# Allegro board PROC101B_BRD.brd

Outline 177.8 x 141 mm; copper layers: TOP, L02_GND1, L03_SIG1, L04_GND2, L05_PWR1, L06_PWR2, L07_GND3, L08_SIG2, L09_GND4, BOTTOM. Coordinates in mm from the lower left corner of the outline.
Outline path: 0,134 0,141 177.8,141 177.8,134 ; 0,134 0,57.03 1.68,57.03 arc(1.82,56.97) 1.88,56.83 1.88,56.38 arc(1.82,56.24) 1.68,56.18 0,56.18 0,52.28 1.68,52.28 arc(1.82,52.22) 1.88,52.08 1.88,51.63 arc(1.82,51.49) 1.68,51.43 0,51.43 0,7 ; 0,134 177.8,134 ; 0,134 177.8,134 ; 177.8,134 177.8,44.11 177.3,43.61 176.2,43.61 arc(175.75,43.16) 176.2,42.71 177.3,42.71 177.8,42.21 177.8,39.36 177.3,38.86 176.2,38.86 arc(175.75,38.41) 176.2,37.96 177.3,37.96 177.8,37.46 177.8,26.96 177.3,26.46 176.2,26.46 arc(175.75,26.01) 176.2,25.56 177.3,25.56 177.8,25.06 177.8,22.21 177.3,21.71 176.2,21.71 arc(175.75,21.26) 176.2,20.81 177.3,20.81 177.8,20.31 177.8,7 ; 0,7 0,0 177.8,0 177.8,7 ; 0,7 177.8,7 ; 0,7 177.8,7

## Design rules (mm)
net group C1: nets C1N C1P
net group C2: nets C2N C2P
net group CLKGEN_REFCLK1N: nets CDC_Y1N CLKGEN_REFCLK1N
net group CLKGEN_REFCLK1P: nets CDC_Y1P CLKGEN_REFCLK1P
net group CPSW_RGMII1_ETH1_CLK: nets CPSW_RGMII1_ETH1_CLK N16248965
net group DDR_CLK: nets DDR_LDQS_N DDR_LDQS_P
net group DP1: nets SERDES_REFCLK0_N_C SERDES_REFCLK0_P_C
net group FT4232_USB_D: nets FT4232_USB_DM FT4232_USB_DP
net group GPMC0_WPN: nets GPMC0_WPN HSE_GPIO0_39
net group MCAN0: nets MCAN0_H MCAN0_L
net group MCAN1: nets MCAN1_H MCAN1_L
net group MCU_SPI0_CLK: nets MCU_SPI0_CLK MCU_SPI0_CLK_R
net group MMC0_CLK: nets MMC0_CLK SOC_MMC0_CLK
net group OSPI_DQS: nets OSPI_DQS OSPI_DQS_SOC
net group PRG0_HSE_ETH1_CLK: nets N16248899 PRG0_HSE_ETH1_CLK
net group PRG0_HSE_ETH2_CLK: nets N16248877 PRG0_HSE_ETH2_CLK
net group PRG1_RGMII1_ETH3_CLK: nets N16248921 PRG1_RGMII1_ETH3_CLK
net group PRG1_RGMII2_ETH2_CLK: nets N16248943 PRG1_RGMII2_ETH2_CLK
net group SERDES_RX: nets SERDES_RXN0 SERDES_RXP0
net group SERDES_TXN0: nets SERDES_TXN0 SERDES_TXN0_C
net group SERDES_TXP0: nets SERDES_TXP0 SERDES_TXP0_C
net group SOC_CLKIN: nets N16248855 SOC_CLKIN
net group SOC_TDO: nets N25395961 SOC_TDO
net group USB0_AB_D: nets USB0_AB_DM USB0_AB_DP
net group USB0_D: nets USB0_DM USB0_DP
net group XDS_USB_D: nets XDS_USB_DM XDS_USB_DP
net group BOOTMODE_U23-T: nets GPMC0_CLK
net group CLKGEN_REFCLK4N: nets CDC_Y4N CLKGEN_REFCLK4N PCIE_SERDES_REFCLK0_N
net group CLKGEN_REFCLK4P: nets CDC_Y4P CLKGEN_REFCLK4P PCIE_SERDES_REFCLK0_P
net group DDR_ADDR: nets DDR_ALERTN
net group DDR_ADDR-1: nets DDR_CSN DDR_ODT DDR_PARITY DDR_TEN
net group DDR_D8-15: nets DDR_DQ8 DDR_DQ9 DDR_DQ10 DDR_DQ11 DDR_DQ12 DDR_DQ13 DDR_DQ14 DDR_DQ15 DDR_UDM DDR_UDQS_N DDR_UDQS_P
net group DDR_DQ0-7: nets DDR_DQ0 DDR_DQ1 DDR_DQ2 DDR_DQ3 DDR_DQ4 DDR_DQ5 DDR_DQ6 DDR_DQ7 DDR_LDM
net group GPMC0_CSN0: nets HSE_GPIO0_41
net group MG1: nets CPSW_ETH1_D0M CPSW_ETH1_D0P CPSW_ETH1_D1M CPSW_ETH1_D1P CPSW_ETH1_D2M CPSW_ETH1_D2P CPSW_ETH1_D3M CPSW_ETH1_D3P
net group MG2: nets PRG0_PRU1GPO0 PRG0_PRU1GPO1 PRG0_PRU1GPO2 PRG0_PRU1GPO3 PRG0_PRU1GPO4 PRG0_PRU1GPO6
net group MG3: nets PRG0_PRU0GPO0 PRG0_PRU0GPO1 PRG0_PRU0GPO2 PRG0_PRU0GPO3 PRG0_PRU0GPO4 PRG0_PRU0GPO6
net group MG4: nets PRG0_PRU1GPO11 PRG0_PRU1GPO12 PRG0_PRU1GPO13 PRG0_PRU1GPO14 PRG0_PRU1GPO15 PRG0_PRU1GPO16
net group MG5: nets GPMC0_AD0 GPMC0_AD1 GPMC0_AD2 GPMC0_AD3 GPMC0_AD4 GPMC0_AD5 GPMC0_AD6 GPMC0_AD7 GPMC0_AD8/FSI_RX0_CLK GPMC0_AD9/FSI_RX0_D0 GPMC0_AD10/FSI_RX0_D1 GPMC0_AD11 GPMC0_AD12 GPMC0_AD13 GPMC0_AD14/FSI_TX0_D0 GPMC0_AD15/FSI_TX0_D1 HSE_GPIO0_31
net group MIPI_TRC: nets MIPI_TRC_DAT00 MIPI_TRC_DAT01 MIPI_TRC_DAT02 MIPI_TRC_DAT03 MIPI_TRC_DAT04 MIPI_TRC_DAT05 MIPI_TRC_DAT06 MIPI_TRC_DAT07 MIPI_TRC_DAT08 MIPI_TRC_DAT09 MIPI_TRC_DAT10 MIPI_TRC_DAT11 MIPI_TRC_DAT12 MIPI_TRC_DAT13 MIPI_TRC_DAT14 MIPI_TRC_DAT15 MIPI_TRC_DAT16 MIPI_TRC_DAT17 MIPI_TRC_DAT18 MIPI_TRC_DAT19 MIPI_TRC_DAT20 MIPI_TRC_DAT21
net group PRG0_RGMII1_TD: nets PRG0_PRU0GPO11 PRG0_PRU0GPO12 PRG0_PRU0GPO13 PRG0_PRU0GPO14 PRG0_PRU0GPO15 PRG0_PRU0GPO16
net group PRG1_ETH2: nets PRG1_ETH2_D0M PRG1_ETH2_D0P PRG1_ETH2_D1M PRG1_ETH2_D1P PRG1_ETH2_D2M PRG1_ETH2_D2P PRG1_ETH2_D3M PRG1_ETH2_D3P
net group PRG1_ETH3: nets PRG1_ETH3_D0M PRG1_ETH3_D0P PRG1_ETH3_D1M PRG1_ETH3_D1P PRG1_ETH3_D2M PRG1_ETH3_D2P PRG1_ETH3_D3M PRG1_ETH3_D3P
net group SOC_TCK: nets N16937764 N16938293 SOC_TCK

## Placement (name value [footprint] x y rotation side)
C1  4700pF  [CAP0402_0-75]  9.53 127.78 180 top
C2  4700pF  [CAP0402_0-75]  19.43 127.78 180 top
C3  0.1uF  [CAP0402_0-75]  16.26 126.13 90 top
C4  0.1uF  [CAP0402_0-75]  102.11 125.87 0 top
C5  0.1uF  [CAP0402_0-75]  141.86 125.87 90 top
C6  1uF  [CAP0402_0-75]  143.13 125.87 270 top
C7  0.1uF  [CAP0402_0-75]  124.46 125.74 0 top
C8  0.1uF  [CAP0402_0-75]  26.03 125.29 270 top
C9  10uF  [CAP0402_0-75]  97.41 116.06 0 top
C10  0.1uF  [CAP0402_0-75]  152.02 125.11 90 top
C11  1uF  [CAP0402_0-75]  75.18 124.47 270 top
C12  0.1uF  [CAP0402_0-75]  76.45 124.47 270 top
C13  0.1uF  [CAP0402_0-75]  77.72 124.47 270 top
C14  0.1uF  [CAP0402_0-75]  37.68 124.71 180 top
C15  1uF  [CAP0402_0-75]  81.59 123.32 180 top
C16  1uF  [CAP0402_0-75]  38.49 123.44 180 top
C17  0.1uF  [CAP0402_0-75]  84.84 122.44 270 top
C18  1uF  [CAP0402_0-75]  72.66 122.24 270 top
C19  0.1uF  [CAP0402_0-75]  73.9 122.24 270 top
C20  22uF  [CAP0603_1]  99.69 119.62 270 top
C21  0.1uF  [CAP0402_0-75]  101.22 119.62 90 top
C22  0.1uF  [CAP0402_0-75]  125.09 119.14 0 top
C23  0.1uF  [CAP0402_0-75]  12.7 118.63 0 top
C24  0.1uF  [CAP0402_0-75]  22.6 118.63 0 top
C25  10uF  [CAP0402_0-75]  29.46 116.73 270 top
C26  0.1uF  [CAP0402_0-75]  54.36 116.73 270 top
C27  0.01uF  [CAP0402_0-75]  105.23 116.39 180 top
C28  22uF  [CAP0603_1]  33.02 114.44 180 top
C29  0.1uF  [CAP0402_0-75]  8.51 112.79 90 top
C30  0.1uF  [CAP0402_0-75]  125.98 112.41 0 top
C31  0.1uF  [CAP0402_0-75]  155.57 111.27 180 top
C32  0.1uF  [CAP0402_0-75]  139.95 110.89 90 top
C33  22uF  [CAP0603_1]  155.69 109.26 0 top
C34  0.1uF  [CAP0402_0-75]  63.47 109.49 270 bottom
C35  0.1uF  [CAP0402_0-75]  40.17 106.95 90 top
C36  0.1uF  [CAP0402_0-75]  38.84 106.95 90 top
C37  10uF  [CAP0402_0-75]  159.13 104.79 90 top
C38  0.1uF  [CAP0402_0-75]  33.74 102.98 180 top
C39  0.1uF  [CAP0402_0-75]  33.74 101.48 180 top
C40  22uF  [CAP0603_1]  149.1 100.6 180 top
C41  0.1uF  [CAP0402_0-75]  45.56 100.59 0 top
C42  0.1uF  [CAP0201_0-5]  85.09 100.57 90 top
C43  0.1uF  [CAP0402_0-75]  33.74 99.98 180 top
C44  0.1uF  [CAP0402_0-75]  45.51 99.13 0 top
C45  0.1uF  [CAP0402_0-75]  123.95 98.95 180 top
C46  22uF  [CAP0603_1]  149.1 98.82 180 top
C47  0.1uF  [CAP0402_0-75]  127.38 97.93 180 top
C48  0.015uF  [CAP0402_0-75]  143.51 96.92 270 top
C49  150pF  [CAP0402_0-75]  144.78 96.92 90 top
C50  0.1uF  [CAP0402_0-75]  134.75 96.79 180 top
C51  0.1uF  [CAP0402_0-75]  41.91 95.77 270 top
C52  1uF  [CAP0402_0-75]  40.14 95.75 270 top
C53  0.01uF  [CAP0402_0-75]  75.82 95.11 90 top
C54  0.1uF  [CAP0402_0-75]  144.02 93.87 0 top
C55  0.1uF  [CAP0402_0-75]  141.6 93.23 270 top
C56  100uF_50V  [CAPAE_D8CASE_8]  165.47 87.1 270 top
C57  0.01uF  [CAP0402_0-75]  144.02 92.6 180 top
C58  1uF  [CAP0402_0-75]  84.26 93.49 270 top
C59  1uF  [CAP0402_0-75]  87.43 93.49 270 top
C60  1uF  [CAP0402_0-75]  88.7 93.49 270 top
C61  1uF  [CAP0402_0-75]  89.97 93.49 270 top
C62  1uF  [CAP0402_0-75]  91.24 93.49 270 top
C63  1uF  [CAP0402_0-75]  94.16 93.49 270 top
C64  1uF  [CAP0402_0-75]  98.81 97.54 0 top
C65  0.1uF  [CAP0402_0-75]  148.59 91.58 0 top
C66  10uF  [CAP0603_1]  148.46 90.06 180 top
C67  0.1uF  [CAP0402_0-75]  31.46 89.6 270 top
C68  1uF  [CAP0402_0-75]  41.78 87.52 90 top
C69  10uF  [CAP1206_2#2]  171.44 84.26 180 top
C70  470uF_10V  [CAPAE_875115252003_330X330_SMD_8-7]  145.7 83.88 0 top
C71  47uF  [CAP1206_2]  171.4 86.52 180 top
C72  0.1uF  [CAP0402_0-75]  132.21 85.22 180 top
C73  0.1uF  [CAP0402_0-75]  33.61 83.62 180 top
C74  4.7uF  [CAP0402_0-75]  108.25 85.42 270 top
C75  0.1uF  [CAP0201_0-5]  106.98 85.42 270 top
C76  0.1uF  [CAP0402_0-75]  33.61 82.12 180 top
C77  10uF  [CAP0402_0-75]  130.96 82.18 0 top
C78  0.1uF  [CAP0402_0-75]  45.43 81.23 0 top
C79  4.7uF  [CAP0402_0-75]  108.46 81.21 180 top
C80  0.1uF  [CAP0402_0-75]  33.61 80.62 180 top
C81  10uF  [CAP1206_2]  158.53 77.79 180 top
C82  10uF  [CAP1206_2]  163.27 77.79 0 top
C83  1uF  [CAP0402_0-75]  45.38 79.77 0 top
C84  22uF  [CAP1206_2#2]  147.09 78.29 0 top
C85  33pF  [CAP0402_0-75]  171.74 78.72 90 top
C86  1uF  [CAP0402_0-75]  107.7 78.37 90 top
C87  4.7uF  [CAP0402_0-75]  109.22 78.37 270 top
C88  4.7uF  [CAP0402_0-75]  72.14 74.34 270 bottom
C89  0.1uF  [CAP0402_0-75]  52.2 89.75 180 top
C90  0.1uF  [CAP0402_0-75]  38.87 76.38 270 top
C91  0.1uF  [CAP0201_0-5]  73.66 77.61 90 top
C92  0.1uF  [CAP0201_0-5]  74.42 77.61 90 top
C93  0.1uF  [CAP0201_0-5]  75.18 77.61 90 top
C94  33pF  [CAP0402_0-75]  148.72 75.45 270 top
C95  4.7uF  [CAP0603_1]  131.98 76.1 90 top
C96  120pF  [CAP0402_0-75]  138.58 76.1 270 top
C97  4.7uF  [CAP0402_0-75]  108.84 75.2 90 top
C98  1uF  [CAP0402_0-75]  107.31 75.07 270 top
C99  10uF  [CAP0402_0-75]  39.45 73.67 180 top
C100  0.22uF  [CAP0201_0-5]  74.85 71.36 0 top
C101  1uF  [CAP0402_0-75]  38.74 71.7 90 top
C102  0.22uF  [CAP0201_0-5]  74.85 70.47 0 top
C103  4.7uF  [CAP0402_0-75]  108.08 69.61 270 top
C104  0.1uF  [CAP0402_0-75]  45.25 68.35 0 top
C105  10uF  [CAP0402_0-75]  47.59 67.62 90 top
C106  1uF  [CAP0402_0-75]  33.52 67.5 180 top
C107  2.2uF  [CAP0603_1]  160.07 67.15 180 top
C108  2.2uF  [CAP0603_1]  163.07 67.15 0 top
C109  0.1uF  [CAP0402_0-75]  136.14 66.94 270 top
C110  1uF  [CAP0402_0-75]  45.28 66.89 0 top
C111  10uF  [CAP0402_0-75]  31.24 67.03 270 top
C112  1uF  [CAP0402_0-75]  33.52 66 180 top
C113  0.01uF  [CAP0402_0-75]  119.63 65.29 270 top
C114  1uF  [CAP0402_0-75]  33.52 64.5 180 top
C115  0.1uF  [CAP0402_0-75]  157.51 64.44 270 top
C116  0.1uF  [CAP0402_0-75]  166.22 64.16 90 top
C117  0.1uF  [CAP0402_0-75]  131.19 64.02 180 top
C118  0.01uF  [CAP0402_0-75]  152.02 62.99 270 top
C119  4.7uF  [CAP0402_0-75]  106.22 72.48 0 bottom
C120  4.7uF  [CAP0402_0-75]  89.28 58.69 270 top
C121  0.1uF  [CAP0201_0-5]  88.51 61.23 180 top
C122  22uF  [CAP0603_1]  19.05 62.5 0 top
C123  47uF  [CAP1206_2]  151.32 59.25 180 top
C124  0.1uF  [CAP0402_0-75]  41.66 60.59 270 top
C125  3900pF  [CAP0402_0-75]  169.22 60.16 0 top
C126  1uF  [CAP0402_0-75]  137.67 60.09 90 top
C127  10uF  [CAP0402_0-75]  22.61 59.83 90 top
C128  0.1uF  [CAP0402_0-75]  25.91 59.45 90 top
C129  2.2uF  [CAP0402_0-75]  133.22 59.45 90 top
C130  4.7pF  [CAP0402_0-75]  168.79 58.65 270 top
C131  0.056uF  [CAP0402_0-75]  156.96 57.07 270 top
C132  0.056uF  [CAP0402_0-75]  166.9 58.13 0 top
C133  12pF  [CAP0201_0-5]  99.72 58.77 180 top
C134  12pF  [CAP0201_0-5]  101.47 58.79 0 top
C135  33pF  [CAP0402_0-75]  155.17 55.53 90 top
C136  0.01uF  [CAP0402_0-75]  154.03 55.56 270 top
C137  1uF  [CAP0402_0-75]  160.07 56.23 90 top
C138  0.47uF  [CAP0603_1#2]  162.42 56.18 270 top
C139  0.1uF  [CAP0402_0-75]  32.97 49.54 0 top
C140  4.7uF  [CAP0402_0-75]  21.67 51.2 270 top
C141  10uF  [CAP0402_0-75]  31.19 52.34 270 top
C143  150uF_10V  [CAPT7343D_3-25]  15.44 43.88 0 top
C144  0.1uF  [CAP0402_0-75]  73.15 49.8 270 top
C145  0.1uF  [CAP0402_0-75]  90.81 49.67 180 top
C146  0.1uF  [CAP0402_0-75]  90.81 48.15 180 top
C147  0.1uF  [CAP0402_0-75]  44.36 48.06 270 bottom
C148  4.7uF  [CAP0402_0-75]  112.33 59.61 270 top
C149  1uF  [CAP0402_0-75]  118.01 60.8 270 top
C150  0.1uF  [CAP0402_0-75]  116.74 60.8 270 top
C151  0.1uF  [CAP0402_0-75]  140.72 45.94 180 top
C152  10uF  [CAP0402_0-75]  170.5 44.08 0 top
C153  1000pF  [CAP1206_1-75]  4.11 61.86 270 top
C154  0.1uF  [CAP0402_0-75]  170.75 42.43 0 top
C155  0.1uF  [CAP0402_0-75]  90.48 37.23 180 top
C156  0.1uF  [CAP0402_0-75]  93.59 35.19 270 top
C157  0.1uF  [CAP0402_0-75]  100.97 35.19 90 top
C158  2.2uF  [CAP0402_0-75]  164.34 35.07 180 top
C159  0.01uF  [CAP0402_0-75]  166.5 35.07 180 top
C160  1000pF  [CAP1206_1-75]  169.42 35.07 90 top
C161  0.1uF  [CAP0402_0-75]  64.49 32.55 180 top
C162  0.1uF  [CAP0402_0-75]  90.48 32.27 180 top
C163  0.1uF  [CAP0402_0-75]  93.59 31.64 270 top
C164  0.1uF  [CAP0402_0-75]  100.97 31.64 90 top
C165  0.1uF  [CAP0402_0-75]  103.61 31.64 90 top
C166  0.01uF  [CAP0402_0-75]  149.13 31.62 90 top
C167  1uF  [CAP0402_0-75]  152.52 31.24 180 top
C168  8.2pF  [CAP0402_0-75]  73.16 30.98 180 top
C169  8.2pF  [CAP0402_0-75]  78.75 30.98 180 top
C170  0.1uF  [CAP0402_0-75]  115.95 28.72 0 top
C171  0.1uF  [CAP0402_0-75]  138.43 28.72 180 top
C172  12pF  [CAP0201_0-5]  163.78 26.15 270 top
C173  0.1uF  [CAP0402_0-75]  120.65 27.57 270 top
C174  1uF  [CAP0402_0-75]  142.41 26.3 180 top
C175  0.01uF  [CAP0402_0-75]  162.31 26.18 90 top
C176  0.01uF  [CAP0402_0-75]  142.41 25.03 180 top
C177  12pF  [CAP0201_0-5]  163.78 24.88 90 top
C178  0.1uF  [CAP0402_0-75]  118.29 52.26 90 top
C179  0.1uF  [CAP0402_0-75]  120.15 24.05 90 top
C180  0.01uF  [CAP0402_0-75]  143.13 23.51 270 top
C181  0.1uF  [CAP0402_0-75]  66.34 23.26 0 top
C182  0.01uF  [CAP0402_0-75]  73.62 22.23 90 top
C183  0.01uF  [CAP0402_0-75]  79.21 22.23 90 top
C184  22uF  [CAP0805_1-5]  42.23 21.99 0 top
C185  0.1uF  [CAP0402_0-75]  163.86 21.77 90 top
C186  1uF  [CAP0402_0-75]  165.15 21.77 270 top
C187  2.2uF  [CAP0402_0-75]  166.41 21.77 270 top
C188  0.1uF  [CAP0402_0-75]  138.56 21.6 0 top
C189  0.1uF  [CAP0402_0-75]  120.07 49.47 180 top
C190  0.01uF  [CAP0402_0-75]  96.44 21.12 270 top
C191  0.01uF  [CAP0402_0-75]  162.43 21.1 90 top
C192  0.1uF  [CAP0402_0-75]  143.65 16.46 90 top
C193  0.1uF  [CAP0402_0-75]  162.47 16.01 90 top
C194  0.1uF  [CAP0402_0-75]  107.81 14.57 270 top
C195  2.2uF  [CAP0402_0-75]  165.35 13.98 90 top
C196  0.1uF  [CAP0402_0-75]  152.67 12.32 180 top
C197  1uF  [CAP0402_0-75]  165.23 10.3 270 top
C198  15pF  [CAP0402_0-75]  163.45 9.54 180 top
C199  0.1uF  [CAP0402_0-75]  91.95 131.46 180 bottom
C200  0.01uF  [CAP0402_0-75]  89.15 126.25 180 bottom
C201  2.2uF  [CAP0402_0-75]  91.95 126.13 0 bottom
C202  0.01uF  [CAP0402_0-75]  97.41 116.06 0 bottom
C203  0.1uF  [CAP0402_0-75]  87 124.35 180 bottom
C204  0.1uF  [CAP0402_0-75]  150.67 122.82 180 bottom
C205  0.1uF  [CAP0402_0-75]  38.5 122.15 180 top
C206  0.1uF  [CAP0402_0-75]  72.63 122.24 270 bottom
C207  0.1uF  [CAP0402_0-75]  43.3 121.71 180 bottom
C208  10uF  [CAP0402_0-75]  75.82 120.66 90 bottom
C209  0.1uF  [CAP0402_0-75]  102.69 121.31 90 bottom
C210  10uF  [CAP0402_0-75]  78.87 119.9 180 bottom
C211  10uF  [CAP0603_1]  142.24 119.39 270 bottom
C212  1uF  [CAP0402_0-75]  71.12 119.06 180 bottom
C213  0.1uF  [CAP0402_0-75]  74.68 117.36 0 bottom
C214  0.1uF  [CAP0402_0-75]  131.57 116.85 180 bottom
C215  0.01uF  [CAP0402_0-75]  29.46 116.73 270 bottom
C216  1uF  [CAP0402_0-75]  38.84 116.08 180 bottom
C217  22uF  [CAP0603_1]  142.62 115.71 0 bottom
C218  0.22uF  [CAP0201_0-5]  77.85 113.17 180 bottom
C219  0.01uF  [CAP0402_0-75]  75.69 113.17 180 bottom
C220  0.1uF  [CAP0402_0-75]  46.31 113.13 180 bottom
C221  0.1uF  [CAP0402_0-75]  135 112.16 270 bottom
C222  0.01uF  [CAP0201_0-5]  94 110.83 180 bottom
C223  0.01uF  [CAP0201_0-5]  87.61 110.83 0 bottom
C224  0.01uF  [CAP0201_0-5]  88.41 110.03 180 bottom
C225  1uF  [CAP0402_0-75]  66.04 109.49 270 bottom
C226  0.1uF  [CAP0402_0-75]  64.77 109.49 270 bottom
C227  0.1uF  [CAP0201_0-5]  86.49 109.36 90 bottom
C228  2.2uF  [CAP0402_0-75]  85.47 109.36 270 bottom
C229  0.01uF  [CAP0201_0-5]  94.68 109.35 270 bottom
C230  22uF  [CAP0603_1]  96.27 109.11 270 bottom
C232  0.01uF  [CAP0201_0-5]  94.68 107.75 270 bottom
C233  0.01uF  [CAP0201_0-5]  86.93 107.75 270 bottom
C234  0.01uF  [CAP0201_0-5]  73.41 107.33 180 bottom
C235  0.1uF  [CAP0402_0-75]  65.66 107.33 90 bottom
C236  0.01uF  [CAP0201_0-5]  93.88 106.95 90 bottom
C237  1uF  [CAP0402_0-75]  40.17 106.92 90 bottom
C238  1uF  [CAP0402_0-75]  38.84 106.92 90 bottom
C239  0.01uF  [CAP0201_0-5]  87.61 106.83 180 bottom
C241  0.01uF  [CAP0201_0-5]  93.2 106.03 0 bottom
C242  0.01uF  [CAP0201_0-5]  86.93 105.35 270 bottom
C243  1uF  [CAP0402_0-75]  142.62 105.04 0 bottom
C244  1uF  [CAP0402_0-75]  81.28 104.92 180 bottom
C245  0.01uF  [CAP0402_0-75]  175.39 104.41 0 bottom
C246  1uF  [CAP0402_0-75]  81.28 103.65 180 bottom
C247  10pF  [CAP0402_0-75]  54.74 103.52 180 bottom
C248  0.01uF  [CAP0201_0-5]  98.93 103.01 0 bottom
C249  1uF  [CAP0402_0-75]  33.77 102.98 180 bottom
C250  0.01uF  [CAP0201_0-5]  86.93 102.95 270 bottom
C251  1uF  [CAP0402_0-75]  81.28 102.38 180 bottom
C252  0.1uF  [CAP0402_0-75]  64.9 101.61 180 bottom
C253  1uF  [CAP0402_0-75]  33.77 101.48 180 bottom
C254  1uF  [CAP0402_0-75]  81.28 101.11 180 bottom
C255  10pF  [CAP0402_0-75]  61.72 100.85 270 bottom
C256  10pF  [CAP0402_0-75]  60.45 100.85 270 bottom
C257  10pF  [CAP0402_0-75]  59.18 100.85 270 bottom
C258  10uF  [CAP0402_0-75]  31.5 100.45 90 bottom
C259  1uF  [CAP0402_0-75]  45.53 100.59 0 bottom
C260  0.1uF  [CAP0402_0-75]  56.26 100.03 0 bottom
C261  1uF  [CAP0402_0-75]  33.77 99.98 180 bottom
C262  10pF  [CAP0402_0-75]  62.99 99.96 270 bottom
C263  10uF  [CAP0402_0-75]  47.46 100.11 270 bottom
C264  1uF  [CAP0402_0-75]  81.28 99.84 180 bottom
C265  1uF  [CAP0402_0-75]  142.24 99.71 270 bottom
C266  1uF  [CAP0402_0-75]  45.5 99.13 0 bottom
C267  1uF  [CAP0402_0-75]  81.28 98.57 180 bottom
C268  0.01uF  [CAP0201_0-5]  86.93 98.15 270 bottom
C269  0.1uF  [CAP0402_0-75]  138.18 97.8 180 bottom
C270  0.1uF  [CAP0201_0-5]  94.39 96.92 0 bottom
C271  0.1uF  [CAP0402_0-75]  172.86 96.66 180 bottom
C272  200pF  [CAP0402_0-75]  154.69 95.9 270 bottom
C274  1uF  [CAP0402_0-75]  41.91 95.8 270 bottom
C275  0.1uF  [CAP0402_0-75]  40.14 95.72 270 bottom
C276  0.1uF  [CAP0402_0-75]  49.4 95.26 270 bottom
C277  2700pF  [CAP0603_1]  131.7 94.76 90 bottom
C278  0.1uF  [CAP0402_0-75]  108.89 93.35 180 bottom
C279  0.1uF  [CAP0402_0-75]  108.89 94.63 180 bottom
C280  1uF  [CAP0402_0-75]  44.26 94.38 90 bottom
C281  10uF  [CAP0402_0-75]  39.07 93.8 180 bottom
C283  0.1uF  [CAP0402_0-75]  131.57 92.6 180 bottom
C284  0.1uF  [CAP0402_0-75]  56.26 92.03 0 bottom
C285  0.1uF  [CAP0402_0-75]  108.92 95.9 180 bottom
C286  1uF  [CAP0402_0-75]  46.92 90.95 180 bottom
C287  1000pF  [CAP1206_1-75]  11.56 90.75 270 bottom
C288  10uF  [CAP0402_0-75]  100.2 90.44 0 bottom
C289  1uF  [CAP0201_0-5]  94.01 78.03 270 bottom
C290  4.7uF  [CAP0402_0-75]  100.2 88.66 0 bottom
C291  0.1uF  [CAP0402_0-75]  116.87 82.01 0 bottom
C292  0.1uF  [CAP0402_0-75]  116.87 80.71 0 bottom
C293  0.1uF  [CAP0402_0-75]  41.78 87.52 90 bottom
C294  1uF  [CAP0402_0-75]  100.2 87.14 0 bottom
C295  1000pF  [CAP1206_1-75]  2.24 88.24 90 bottom
C296  0.1uF  [CAP0402_0-75]  116.81 79.44 0 bottom
C297  1uF  [CAP0402_0-75]  33.64 83.62 180 bottom
C298  1uF  [CAP0201_0-5]  87.01 80.98 0 bottom
C299  4.7uF  [CAP0402_0-75]  104.83 78.62 270 bottom
C300  0.1uF  [CAP0201_0-5]  103.58 78.6 270 bottom
C301  1uF  [CAP0402_0-75]  33.64 82.12 180 bottom
C302  0.1uF  [CAP0201_0-5]  93.46 81.78 0 bottom
C303  0.1uF  [CAP0201_0-5]  91.86 81.78 0 bottom
C304  0.1uF  [CAP0201_0-5]  88.66 81.78 180 bottom
C305  10uF  [CAP0402_0-75]  31.37 81.09 90 bottom
C306  1uF  [CAP0402_0-75]  45.4 81.23 0 bottom
C307  0.1uF  [CAP0201_0-5]  94.93 81.1 270 bottom
C308  0.1uF  [CAP0201_0-5]  90.93 81.1 270 bottom
C309  0.1uF  [CAP0201_0-5]  90.13 81.1 90 bottom
C310  0.1uF  [CAP0201_0-5]  93.46 80.98 180 bottom
C311  0.1uF  [CAP0201_0-5]  91.86 80.98 180 bottom
C312  0.1uF  [CAP0201_0-5]  88.66 80.98 0 bottom
C313  1uF  [CAP0402_0-75]  33.64 80.62 180 bottom
C314  0.1uF  [CAP0201_0-5]  95.73 80.3 270 bottom
C315  0.1uF  [CAP0201_0-5]  88.62 80.18 180 bottom
C316  10uF  [CAP0402_0-75]  47.71 80.49 270 bottom
C317  0.1uF  [CAP0201_0-5]  93.46 80.18 0 bottom
C318  0.1uF  [CAP0201_0-5]  91.86 80.18 0 bottom
C319  0.1uF  [CAP0201_0-5]  87.06 80.18 180 bottom
C320  0.1uF  [CAP0402_0-75]  45.37 79.77 0 bottom
C321  0.1uF  [CAP0201_0-5]  94.93 79.5 270 bottom
C322  0.01uF  [CAP0201_0-5]  94.13 79.5 90 bottom
C323  0.1uF  [CAP0201_0-5]  90.13 79.5 90 bottom
C324  0.1uF  [CAP0201_0-5]  91.86 79.38 180 bottom
C325  0.1uF  [CAP0201_0-5]  88.66 79.38 0 bottom
C326  0.1uF  [CAP0201_0-5]  87.06 79.38 0 bottom
C327  4.7uF  [CAP0402_0-75]  76.71 81.19 270 bottom
C328  0.1uF  [CAP0201_0-5]  95.73 78.7 270 bottom
C329  0.1uF  [CAP0201_0-5]  93.33 78.7 90 bottom
C330  0.1uF  [CAP0201_0-5]  91.18 78.7 90 bottom
C331  0.1uF  [CAP0201_0-5]  94.93 78.58 0 bottom
C332  0.1uF  [CAP0201_0-5]  89.46 78.58 0 bottom
C333  0.1uF  [CAP0201_0-5]  87.86 78.58 0 bottom
C334  10uF  [CAP0402_0-75]  103.9 86.02 0 bottom
C335  4.7uF  [CAP0402_0-75]  103.9 84.75 0 bottom
C336  1uF  [CAP0402_0-75]  103.9 83.48 0 bottom
C337  0.1uF  [CAP0201_0-5]  95.86 77.78 0 bottom
C338  0.1uF  [CAP0201_0-5]  94.51 77.1 180 bottom
C339  0.1uF  [CAP0201_0-5]  89.46 77.78 180 bottom
C340  0.1uF  [CAP0201_0-5]  77.98 81.19 270 bottom
C341  4.7uF  [CAP0402_0-75]  76.28 77.61 0 bottom
C342  0.1uF  [CAP0201_0-5]  90.38 77.23 270 bottom
C343  0.1uF  [CAP0201_0-5]  95.86 77.23 0 bottom
C344  0.01uF  [CAP0201_0-5]  88.66 77.23 0 bottom
C345  0.1uF  [CAP0201_0-5]  91.98 77.22 270 bottom
C346  0.1uF  [CAP0201_0-5]  91.18 77.22 270 bottom
C347  0.01uF  [CAP0201_0-5]  93.46 77.1 0 bottom
C348  1uF  [CAP0201_0-5]  87.06 77.5 180 bottom
C349  1uF  [CAP0402_0-75]  38.87 76.41 270 bottom
C350  0.01uF  [CAP0201_0-5]  86.38 76.21 90 bottom
C351  0.1uF  [CAP0201_0-5]  94.93 76.18 90 bottom
C352  0.1uF  [CAP0201_0-5]  93.33 76.18 90 bottom
C353  0.01uF  [CAP0201_0-5]  92.53 76.18 90 bottom
C354  0.1uF  [CAP0201_0-5]  91.06 76.18 180 bottom
C355  0.01uF  [CAP0201_0-5]  89.46 76.18 0 bottom
C356  0.01uF  [CAP0201_0-5]  87.86 76.18 180 bottom
C357  1uF  [CAP0201_0-5]  88.78 74.58 90 bottom
C358  0.1uF  [CAP0201_0-5]  81.67 76.43 180 bottom
C359  0.1uF  [CAP0201_0-5]  96.53 75.5 270 bottom
C360  0.1uF  [CAP0201_0-5]  87.18 75.5 90 bottom
C361  0.1uF  [CAP0201_0-5]  95.73 75.38 0 bottom
C362  0.01uF  [CAP0201_0-5]  88.66 75.38 0 bottom
C363  4.7uF  [CAP0402_0-75]  111.51 75.2 90 bottom
C364  4.7uF  [CAP0402_0-75]  104.98 75.15 90 bottom
C365  0.1uF  [CAP0201_0-5]  115.95 75.07 0 bottom
C366  1uF  [CAP0402_0-75]  103.48 75.07 270 bottom
C367  0.1uF  [CAP0201_0-5]  110.11 75.06 90 bottom
C368  0.01uF  [CAP0201_0-5]  92.78 74.83 270 bottom
C369  10uF  [CAP0402_0-75]  38.6 74.82 180 bottom
C370  0.1uF  [CAP0201_0-5]  93.66 74.91 225 bottom
C371  0.1uF  [CAP0201_0-5]  89.66 74.5 135 bottom
C372  0.1uF  [CAP0201_0-5]  90.81 74.31 180 bottom
C373  0.01uF  [CAP0201_0-5]  93.46 74.03 180 bottom
C374  0.1uF  [CAP0201_0-5]  95.73 73.9 270 bottom
C375  0.01uF  [CAP0201_0-5]  87.26 74.11 225 bottom
C376  0.1uF  [CAP0201_0-5]  95.05 73.88 315 bottom
C377  4.7uF  [CAP0402_0-75]  115.95 73.8 0 bottom
C378  0.1uF  [CAP0201_0-5]  88.54 73.23 0 bottom
C379  0.1uF  [CAP0201_0-5]  89.46 73.78 180 bottom
C380  0.01uF  [CAP0201_0-5]  87.26 73.31 225 bottom
C381  0.1uF  [CAP0201_0-5]  91.71 72.98 270 bottom
C382  0.1uF  [CAP0201_0-5]  94.26 73.1 315 bottom
C383  0.1uF  [CAP0201_0-5]  92.55 72.98 0 bottom
C384  0.1uF  [CAP0402_0-75]  72.15 71.25 0 bottom
C385  0.1uF  [CAP0402_0-75]  38.74 71.73 90 bottom
C387  0.1uF  [CAP0201_0-5]  106.79 69.53 270 top
C388  0.1uF  [CAP0402_0-75]  72.15 69.98 0 bottom
C389  1uF  [CAP0402_0-75]  45.25 68.35 0 bottom
C390  1uF  [CAP0201_0-5]  94.13 76.18 90 bottom
C391  1uF  [CAP0201_0-5]  91.26 75.3 135 bottom
C392  0.1uF  [CAP0402_0-75]  33.49 67.5 180 bottom
C393  0.1uF  [CAP0402_0-75]  139.32 67.45 180 bottom
C394  0.1uF  [CAP0402_0-75]  45.31 66.89 0 bottom
C395  0.1uF  [CAP0402_0-75]  33.49 66 180 bottom
C396  1uF  [CAP0201_0-5]  89.66 72.9 135 bottom
C397  0.1uF  [CAP0402_0-75]  33.49 64.5 180 bottom
C398  4.7uF  [CAP0402_0-75]  89.33 61.2 180 bottom
C399  0.1uF  [CAP0201_0-5]  87.76 62.49 270 bottom
C400  3.3uF  [CAP0603_1]  92.56 67.79 90 bottom
C401  1uF  [CAP0402_0-75]  41.66 60.59 270 bottom
C402  0.01uF  [CAP0402_0-75]  22.61 59.83 90 bottom
C403  0.01uF  [CAP0402_0-75]  140.59 57.16 0 bottom
C404  0.1uF  [CAP0402_0-75]  79.25 56.91 90 bottom
C405  0.1uF  [CAP0402_0-75]  79.25 54.5 270 bottom
C406  0.01uF  [CAP0402_0-75]  170.94 53.86 0 bottom
C407  0.1uF  [CAP0402_0-75]  139.19 53.35 0 bottom
C408  0.1uF  [CAP0402_0-75]  132.08 51.83 0 bottom
C409  0.1uF  [CAP0402_0-75]  140.34 51.32 90 bottom
C410  0.1uF  [CAP0402_0-75]  113.54 50.78 270 bottom
C411  0.1uF  [CAP0402_0-75]  60.96 50.69 90 bottom
C412  0.1uF  [CAP0402_0-75]  138.68 50.43 270 bottom
C413  0.1uF  [CAP0402_0-75]  144.4 50.05 180 bottom
C414  0.1uF  [CAP0402_0-75]  133.22 48.91 90 bottom
C415  4.7uF  [CAP0402_0-75]  99.8 47.36 180 bottom
C416  0.1uF  [CAP0402_0-75]  132.59 46.5 0 bottom
C417  0.1uF  [CAP0402_0-75]  110.87 46.26 270 bottom
C418  0.1uF  [CAP0402_0-75]  99.8 46.08 180 bottom
C419  0.1uF  [CAP0402_0-75]  148.08 44.97 270 bottom
C420  0.1uF  [CAP0402_0-75]  132.59 44.97 0 bottom
C421  0.1uF  [CAP0402_0-75]  27.05 44.34 270 bottom
C422  0.1uF  [CAP0402_0-75]  132.84 43.32 270 bottom
C423  0.1uF  [CAP0402_0-75]  148.72 41.92 180 bottom
C424  0.1uF  [CAP0402_0-75]  154.69 41.54 270 bottom
C425  0.1uF  [CAP0402_0-75]  132.84 41.42 270 bottom
C426  0.1uF  [CAP0402_0-75]  35.43 40.27 90 bottom
C427  0.1uF  [CAP0402_0-75]  116 39.84 90 bottom
C428  1uF  [CAP0402_0-75]  114.15 39.84 90 bottom
C429  0.1uF  [CAP0402_0-75]  155.07 39.77 180 bottom
C430  2.2uF  [CAP0402_0-75]  118.01 39.64 180 bottom
C431  0.1uF  [CAP0402_0-75]  11.05 39 90 bottom
C432  0.01uF  [CAP0402_0-75]  9.53 39 90 bottom
C433  18pF  [CAP0402_0-75]  132.33 38.95 270 bottom
C434  0.1uF  [CAP0402_0-75]  104.27 37.99 270 bottom
C435  0.1uF  [CAP0402_0-75]  20.07 37.99 90 bottom
C436  0.01uF  [CAP0402_0-75]  18.8 37.99 90 bottom
C437  0.1uF  [CAP0402_0-75]  118.4 37.1 0 bottom
C438  2.2uF  [CAP0402_0-75]  120.52 36.67 90 bottom
C439  18pF  [CAP0402_0-75]  132.33 36.16 90 bottom
C440  0.1uF  [CAP0402_0-75]  136.4 35.07 90 bottom
C441  3.3uF  [CAP0603_1]  144.5 34.25 270 bottom
C442  0.1uF  [CAP0402_0-75]  140.97 34.81 90 bottom
C443  0.1uF  [CAP0402_0-75]  118.24 32.48 0 bottom
C444  0.01uF  [CAP0402_0-75]  59.94 31.89 180 bottom
C445  0.1uF  [CAP0402_0-75]  127.38 31 270 bottom
C446  0.1uF  [CAP0402_0-75]  45.97 30.24 270 bottom
C447  0.1uF  [CAP0402_0-75]  160.99 30.24 270 bottom
C448  47uF  [CAP1206_2]  5.33 26.94 180 bottom
C449  0.1uF  [CAP0402_0-75]  10.92 26.43 270 bottom
C450  0.01uF  [CAP0402_0-75]  9.65 26.43 270 bottom
C451  2.2uF  [CAP0402_0-75]  40.77 26.18 180 bottom
C452  2.2uF  [CAP0603_1]  56.64 25.29 180 bottom
C453  0.1uF  [CAP0402_0-75]  143.13 23.51 90 bottom
C454  1uF  [CAP0402_0-75]  7.87 23.26 90 bottom
C455  0.1uF  [CAP0402_0-75]  24.03 22.48 0 bottom
C456  0.01uF  [CAP0402_0-75]  77.31 22.23 90 bottom
C457  0.01uF  [CAP0402_0-75]  71.72 22.23 90 bottom
C458  22uF  [CAP0805_1-5]  54.86 21.48 90 bottom
C459  1uF  [CAP0402_0-75]  15.62 21.48 90 bottom
C460  1uF  [CAP0402_0-75]  8.64 21.35 90 bottom
C461  0.1uF  [CAP0402_0-75]  123.14 57.47 270 bottom
C462  1uF  [CAP0402_0-75]  6.99 20.08 180 bottom
C463  1uF  [CAP0402_0-75]  6.99 18.76 180 bottom
C464  0.1uF  [CAP0402_0-75]  123.4 53.24 180 bottom
C465  0.1uF  [CAP0402_0-75]  123.57 18.05 90 bottom
C466  0.1uF  [CAP0402_0-75]  132.47 17.9 90 bottom
C467  0.1uF  [CAP0402_0-75]  116.02 17.86 90 bottom
C468  0.1uF  [CAP0402_0-75]  138.29 17.43 90 bottom
C469  0.1uF  [CAP0402_0-75]  82.04 17.29 180 bottom
C470  1uF  [CAP0402_0-75]  24.26 16.27 180 bottom
C471  1uF  [CAP0402_0-75]  15.24 16.14 180 bottom
C472  0.1uF  [CAP0402_0-75]  82.02 15.99 180 bottom
C473  4.7uF  [CAP0603_1]  8.76 15.76 0 bottom
C474  2.2uF  [CAP0603_1]  8.64 10.99 270 bottom
C475  0.1uF  [CAP0201_0-5]  90.47 75.3 90 bottom
C476  0.1uF  [CAP0402_0-75]  94.39 42.56 90 top
C477  0.1uF  [CAP0402_0-75]  102.13 38.42 0 top
C478  1000pF  [CAP1206_1-75]  172.82 108.42 270 bottom
C479  0.1uF  [CAP0402_0-75]  113.75 109.22 180 top
C482  47uF  [CAP1206_2]  120.11 100.07 90 top
C483  0.1uF  [CAP0201_0-5]  121.63 99.43 90 top
C484  0.1uF  [CAP0201_0-5]  122.52 99.43 90 top
C485  0.1uF  [CAP0402_0-75]  126.75 48.39 90 top
C486  10uF  [CAP0402_0-75]  131.7 83.69 0 top
C487  10pF  [CAP0402_0-75]  112.9 80.53 0 bottom
C488  10pF  [CAP0402_0-75]  108.95 85.3 90 bottom
C491  10pF  [CAP0402_0-75]  100.73 64.13 270 bottom
C492  10pF  [CAP0402_0-75]  102.6 67.46 270 bottom
C493  10pF  [CAP0402_0-75]  105.39 66.94 270 bottom
C494  0.1uF  [CAP0402_0-75]  133.44 99.45 90 top
C495  0.1uF  [CAP0402_0-75]  123.57 103.62 180 top
C509  0.47uF  [CAP0402_0-75]  53.49 50.63 270 top
C513  0.47uF  [CAP0402_0-75]  45.26 51.67 270 top
C517  0.47uF  [CAP0402_0-75]  51.97 60.92 0 top
C519  0.47uF  [CAP0402_0-75]  49.94 60.92 180 top
C520  4.7uF  [CAP0402_0-75]  46.41 51.67 270 top
C521  4.7uF  [CAP0402_0-75]  52.35 50.63 270 top
C522  4.7uF  [CAP0402_0-75]  51.97 59.77 0 top
C523  4.7uF  [CAP0402_0-75]  49.94 59.77 180 top
C524  0.1uF  [CAP0402_0-75]  51.21 50.63 270 top
C525  0.1uF  [CAP0402_0-75]  51.97 58.63 0 top
C526  0.1uF  [CAP0402_0-75]  49.94 58.63 180 top
C527  0.1uF  [CAP0402_0-75]  47.55 51.67 270 top
C529  0.1uF  [CAP0402_0-75]  78.65 39.73 180 top
C532  27pF  [CAP0402_0-75]  47.65 50.12 0 top
C533  27pF  [CAP0402_0-75]  49.56 50.12 180 top
C534  0.1uF  [CAP0402_0-75]  111.22 109.67 270 bottom
C535  2700pF  [CAP0603_1]  110.26 107.97 180 bottom
C536  1uF  [CAP0402_0-75]  58.93 108.86 180 top
C537  0.1uF  [CAP0402_0-75]  60.93 108.86 180 top
C538  0.1uF  [CAP0402_0-75]  58.93 103.76 180 top
C539  2.2uF  [CAP0603_1]  164.64 60.45 270 bottom
D1  SMCJ64CA  [DIO_SMC]  172.03 103.34 0 top
D2  S1G-13-F  [DIO_SMA]  159.95 99.2 90 top
D3  PMEG045V150EPDAZ  [CFP15_PMEG045V150EPD_0-9]  169.85 95.6 270 top
D4  XBS104S13R  [DIO_SOD323_1]  159.09 70.58 0 top
D5  XBS104S13R  [DIO_SOD323_1]  164.05 70.58 180 top
D6  TPD1E10B06DPYR  [DIO_DFN0402_0-5]  170.63 45.73 0 top
D7  BZX84C6V8LT1G  [SOT23-123_1-2]  3.94 38.88 90 bottom
D8  TPD1E10B06DPYR  [DIO_DFN0402_0-5]  121.92 17.92 90 bottom
D9  TPD1E10B06DPYR  [DIO_DFN0402_0-5]  129.29 17.78 90 bottom
D10  TPD1E10B06DPYR  [DIO_DFN0402_0-5]  136.73 17.69 90 bottom
D11  TPD1E10B06DPYR  [DIO_DFN0402_0-5]  114.63 17.61 90 bottom
F1  10A  [FUSE_397_410X110_SMD_2-9]  164.39 103.67 270 top
FB1  120E  [IND0603_1]  17.17 123.2 180 top
FB2  120E  [IND0603_1]  24.09 116.98 180 top
FB3  120E  [IND0603_1]  110.03 85.42 90 top
FB4  26E  [IND0603_1]  72.49 78.53 0 bottom
FB5  120E  [IND0603_1]  109.86 69.61 90 top
FB6  120E  [IND0603_1]  91.06 58.56 90 top
FB8  120E  [IND0603_1]  170.75 26.68 180 top
FB9  120E  [IND0603_1]  41.4 25.29 90 top
FB11  120E  [IND0603_1]  83.19 109.87 0 bottom
FB12  120E  [IND0603_1]  67.97 109.49 180 bottom
FB13  120E  [IND0603_1]  108.66 80.25 270 bottom
FB14  120E  [IND0603_1]  26.11 77.55 180 bottom
FB15  120E  [IND0603_1]  72.39 82.84 0 bottom
FB16  26E  [IND0603_1]  72.47 81.07 0 bottom
FB17  26E  [IND0603_1]  115.95 71.49 180 bottom
FB18  120E  [IND0603_1]  111.25 71.34 90 bottom
FB19  120E  [IND0603_1]  26.78 72.18 180 bottom
FB20  120E  [IND0603_1]  91.29 59.55 180 bottom
FB21  120E  [IND0603_1]  59.18 51.81 90 bottom
FB23  220E  [IND0402_0-6]  130.94 42.94 180 bottom
FB24  220E  [IND0402_0-6]  130.94 41.16 180 bottom
FB25  120E  [IND0603_1]  61.61 111.35 180 top
FB26  120E  [IND0603_1]  12.71 111.96 0 top
FL7  4.7uF  [EMIFIL_NFM21P_0805_1]  33.48 52.08 90 top
FL17  0.47uF  [EMIFIL_NFM21P_0805]  49.41 62.82 0 top
FL18  0.47uF  [EMIFIL_NFM21P_0805]  53.35 62.82 180 top
FL19  0.47uF  [EMIFIL_NFM21P_0805]  55.52 50.12 90 top
FL20  0.47uF  [EMIFIL_NFM21P_0805]  43.33 51.39 90 top
FL22  90E  [IND4_ACM2012_90X50_SMD_1-3]  8.48 56.53 180 bottom
J1  HDR_2X12  [HDR_2X12_TSW-112-07-D_S_T_8-6]  141.73 128.67 0 top
J2  CON_XMC_5X30_F  [CON_XMC5X30_SEAF-30-06-05-2-A_S_S_S_6-4]  55.5 129.81 180 top
J3  HDR_2X10  [HDR_2X10_TSW_100_S_T]  104.65 128.16 180 top
J4  HDR_1X5  [HDR_5X1_100_S_T_11-2]  129.16 124.73 180 top
J5  HDR_1X3  [HDR_3X1_100_S_T]  109.93 124.39 0 top
J6  CON_PWRJACK2_PJ-080BH  [CON_PWRJACK2_PJ-080BH_P_R_T_13-4]  164.62 117.64 90 top
J7  HDR_2X5  [HDR_5X2_100_S_T_8-6]  3.56 123.33 90 top
J8  HDR_2X1  [HDR_2X1_100_S_T_10-8]  88.65 116.6 0 top
J9  HDR_1X2  [HDR_1X2_68002-202_S_T_8-6]  24.51 114.57 0 top
J10  HDR_1X2  [HDR_1X2_68002-202_S_T_8-6]  13.84 114.19 0 top
J11  HDR_2X1  [HDR_2X1_100_S_T_10-8]  151.89 113.3 0 top
J12  HDR_2X1  [HDR_2X1_100_S_T]  122.3 113.81 90 top
J13  HDR_2X1  [HDR_2X1_100_S_T_10-8]  132.84 108.85 0 top
J14  CON_RJ45-14_LPJG16314A4NL  [CON_RJ45-14_LPJG16314A4NL_S_R_T_13-6]  15.95 107.66 270 top
J15  HDR_2X1  [HDR_2X1_100_S_T]  59.44 95.39 90 top
J16  HDR_2X1  [HDR_2X1_100_S_T]  62.74 95.39 90 top
J17  HDR_2X1  [HDR_2X1_100_S_T]  65.91 95.39 90 top
J18  HDR_2X1  [HDR_2X1_100_S_T]  69.09 95.39 90 top
J19  HDR_2X1  [HDR_2X1_100_S_T_10-8]  139.57 89.93 0 top
J20  HDR_2X1  [HDR_2X1_100_S_T_10-8]  128.91 85.74 0 top
J21  CON_RJ45-28_LPJG17512AONL  [CON_RJ45-28_LPJG17512_S_R_T_25-3]  11.77 78.69 270 top
J22  HDR_2X1  [HDR_2X1_100_S_T_10-8]  127.76 66.31 270 top
J23  HDR_2X3  [HDR_2X3_TSW-103-07-D_S_T_8-4]  7.21 47.06 180 top
J24  CON_MUSB-AB_5_F  [CON_USBAB5_ZX62RD-AB-5P8_S_R_S_3-2]  1.62 54.23 270 top
J25  HDR_2X10  [HDR_2X10_FTR-110-51-D-06_S_S_8-7]  69.98 44.08 180 top
J26  CON_MUSB-B_5_F  [CON_MUSBB5_1051640001_S_R_S_2-5]  175.83 40.78 90 top
J27  CON_MINIPCI_2X32  [CON_MINIPCI2X32_PCIE-064-02_S_S_T_11]  9.78 33.95 0 top
J28  CON_MUSB-B_5_F  [CON_MUSBB5_1051640001_S_R_S_2-5]  175.83 23.64 90 top
J29  HDR_1X3  [HDR_3X1_100_S_T]  111.51 14.75 90 top
J30  HDR_2X1  [HDR_2X1_100_S_T_10-8]  53.59 10.05 180 top
J31  HDR_1X3  [HDR_3X1_100_S_T]  20.07 131.84 180 top
J32  HDR_1X3  [HDR_3X1_100_S_T]  10.16 131.84 180 top
J33  CON_PMC_2X30_F  [CON_PMC2X30_QSH-030-01-D-A_S_S_S_3-3]  69.98 44.08 0 bottom
J34  HDR_1X3  [HDR_3X1_100_S_T]  42.42 40.15 180 bottom
J35  HDR_1X3  [HDR_3X1_100_S_T]  22.3 41.47 180 bottom
J36  CON_FLEX_1X14_10051922  [CON_FLEX1X14_10051922_S_R_S]  3.05 19.06 90 bottom
J37  CON_SDCARD10_DM3BT-DSF-PEJS  [CON_SD10_DM3BT-DSF-PEJS_S_R_S_2-4]  41.78 16.52 180 bottom
J38  CON_FLEX_40X1_FH12A-40S-0.5SH  [CON_FLEX40X1_FH12A_S_R_S]  73.66 10.3 180 bottom
J39  HDR_2X1  [HDR_2X1_100_S_T_10-8]  158.95 44.64 90 top
J40  HDR_2X1  [HDR_2X1_100_S_T_10-8]  164.16 44.64 90 top
L1  1uH  [IND_744316100_230X220_SMD_4-3]  37.47 117.36 270 top
L2  1uH  [IND_744316100_230X220_SMD_4-3]  96.9 124.06 0 top
L3  6.8uH  [IND_74439346068_260X270_SMD_6-1]  154.31 95.77 90 top
L4  0.47uH  [IND_744373460047_270X270_SMD_3]  127.4 77.25 90 top
L5  1uH  [IND_744316100_230X220_SMD_4-3]  172.21 72.4 0 top
L6  0.47uH  [IND_744373460047_270X270_SMD_3]  149.1 69.61 0 top
L7  1uH  [IND_744316100_230X220_SMD_4-3]  14.61 59.2 90 top
L8  0.47uH  [IND_744373460047_270X270_SMD_3]  137.54 117.87 270 bottom
L9  10uH  [IND_74438336100_130X130_SMD_2]  55.88 16.52 180 bottom
LD1  150080VS75000  [LED_150080VS75000_80X50_SMD_0-8]  30.99 126.25 0 top
LD2  150080VS75000  [LED_150080VS75000_80X50_SMD_0-8]  158.5 126 180 top
LD3  150080VS75000  [LED_150080VS75000_80X50_SMD_0-8]  121.92 122.95 270 top
LD4  150080VS75000  [LED_150080VS75000_80X50_SMD_0-8]  149.22 103.01 0 top
LD5  150080RS75000  [LED_150080VS75000_80X50_SMD_0-8]  159.78 94.03 90 top
LD6  150080VS75000  [LED_150080VS75000_80X50_SMD_0-8]  174.86 93.11 90 top
LD7  150080VS75000  [LED_150080VS75000_80X50_SMD_0-8]  135.18 86.28 180 top
LD8  150080VS75000  [LED_150080VS75000_80X50_SMD_0-8]  138.81 63.9 270 top
LD9  150080VS75000  [LED_150080VS75000_80X50_SMD_0-8]  171.71 63.63 0 top
LD10  150080VS75000  [LED_150080VS75000_80X50_SMD_0-8]  8.68 63.15 0 top
LD11  150080VS75000  [LED_150080VS75000_80X50_SMD_0-8]  20.62 88.28 90 top
LD12  150080VS75000  [LED_150080VS75000_80X50_SMD_0-8]  22.66 88.28 90 top
LD13  150080VS75000  [LED_150080VS75000_80X50_SMD_0-8]  50.09 69.64 90 top
LD14  150080VS75000  [LED_150080VS75000_80X50_SMD_0-8]  52.12 69.64 90 top
LD15  150080VS75000  [LED_150080VS75000_80X50_SMD_0-8]  161.8 52.21 0 top
LD16  150080VS75000  [LED_150080VS75000_80X50_SMD_0-8]  36.35 74.03 90 top
LD17  150080VS75000  [LED_150080VS75000_80X50_SMD_0-8]  34.32 74.03 90 top
LD18  150080VS75000  [LED_150080VS75000_80X50_SMD_0-8]  32.28 74 90 top
LD19  150080VS75000  [LED_150080VS75000_80X50_SMD_0-8]  30.25 74 90 top
LD20  150060VS75000  [LED_150060SS75000_70X40_SMD_0-8]  141.39 32.4 0 top
LD21  150080VS75000  [LED_150080VS75000_80X50_SMD_0-8]  137.03 31.51 90 top
LD22  150060RS55040  [LED_150060RS55040_70X40_SMD_0-5]  141.39 30.24 0 top
LD23  150080RS75000  [LED_150080VS75000_80X50_SMD_0-8]  101.8 18.97 90 top
LD24  150080VS75000  [LED_150080VS75000_80X50_SMD_0-8]  53.98 18.81 270 top
LD25  150080VS75000  [LED_150080VS75000_80X50_SMD_0-8]  16.76 10.68 0 top
LD26  150080VS75000  [LED_150080VS75000_80X50_SMD_0-8]  95.38 10.4 270 top
NOREF  -  []  0 141 0 top
NOREF#2  -  [unnamed#2]  4.32 126.63 0 top
NOREF#3  -  []  325.36 -31.73 0 top
NOREF#4  -  [unnamed#2]  4.32 3.5 0 top
NOREF#5  -  []  -320.36 -8.97 0 top
NOREF#6  -  [unnamed#2]  9.4 137.5 0 top
NOREF#7  -  [unnamed#2]  169.93 137.5 180 top
NOREF#8  -  []  44.53 -0.08 0 top
NOREF#9  -  []  177.8 0 90 top
NOREF#10  -  [unnamed#2]  80.9 130.44 0 top
NOREF#11  -  [unnamed#2]  175.01 126.63 0 top
NOREF#12  -  [unnamed#2]  29.84 130.44 0 top
NOREF#13  -  [unnamed#2]  175.01 3.5 180 top
NOREF#14  -  [unnamed#2]  175.01 14.37 0 top
NOREF#15  -  [unnamed#2]  4.32 137.5 0 top
NOREF#16  -  [unnamed#2]  90.04 10.56 0 top
NOREF#17  -  [unnamed#2]  175.01 137.5 180 top
NOREF#18  -  []  152.39 7 0 top
NOREF#19  -  [unnamed#2]  9.4 3.5 0 top
NOREF#20  -  [unnamed#2]  99.69 130.44 0 top
NOREF#21  -  [unnamed#2]  175.01 10.56 0 top
NOREF#22  -  []  177.8 7 90 top
NOREF#23  -  [unnamed#2]  169.93 3.5 180 top
NOREF#24  -  [unnamed#2]  175.01 130.44 0 top
NOREF#25  -  []  -283.09 185.17 0 top
NOREF#26  -  [unnamed#2]  4.32 130.44 0 top
NOREF#27  -  [unnamed#2]  4.32 10.56 0 top
NOREF#28  -  []  -248.67 -157.73 0 top
NOREF#29  -  [unnamed#2]  134.06 130.44 0 top
NOREF#30  -  [unnamed#3]  91.06 77.1 270 top
NOREF#31  -  []  33.99 -94.82 0 top
NOREF#32  -  [unnamed#2]  9.4 137.5 180 bottom
NOREF#33  -  [unnamed#2]  169.93 137.5 0 bottom
NOREF#34  -  [unnamed#2]  169.93 3.5 0 bottom
NOREF#35  -  [unnamed#2]  4.32 126.63 180 bottom
NOREF#36  -  [unnamed#2]  9.4 3.5 180 bottom
NOREF#37  -  [unnamed#2]  175.01 14.37 180 bottom
NOREF#38  -  [unnamed#2]  175.01 126.63 180 bottom
Q1  BSS138LT1G  [SOT23-123_1-2]  124.97 123.2 180 top
Q2  BSS138LT1G  [SOT23-123_1-2]  158.75 122.7 90 top
Q3  BSS138LT1G  [SOT23-123_1-2]  31.17 110.95 270 top
Q4  BSS138LT1G  [SOT23-123_1-2]  9.14 87.28 270 top
Q5  BSS138LT1G  [SOT23-123_1-2]  135.44 83.23 90 top
Q6  BSS138LT1G  [SOT23-123_1-2]  135.76 63.77 0 top
Q7  BSS138LT1G  [SOT23-123_1-2]  8.25 60.04 180 top
Q8  IRLML6401  [TO_SOT23-123#2]  129.21 26.17 270 top
Q9  IRLML6401  [TO_SOT23-123]  129.41 22.24 270 top
Q10  IRLML6401  [TO_SOT23-123]  125.22 22.11 270 top
Q11  BSS138LT1G  [SOT23-123_1-2]  28.32 123.84 90 bottom
Q12  BSS138LT1G  [SOT23-123_1-2]  27.38 112.28 180 bottom
Q13  BSS138LT1G  [SOT23-123_1-2]  32.42 95.06 180 bottom
Q14  BSS138LT1G  [SOT23-123_1-2]  11.22 68.63 90 bottom
Q15  BSS138LT1G  [SOT23-123_1-2]  3.4 72.24 0 bottom
Q16  BSS138LT1G  [SOT23-123_1-2]  2.69 78.12 0 bottom
Q17  IRLML6401  [TO_SOT23-123]  129.41 22.24 270 bottom
Q18  BSS138LT1G  [SOT23-123_1-2]  100.13 15.51 90 bottom
Q19  BSS138LT1G  [SOT23-123_1-2]  95.91 15.51 270 bottom
Q20  BSS138LT1G  [SOT23-123_1-2]  15.54 87.3 270 top
Q21  BSS138LT1G  [SOT23-123_1-2]  14.33 84.76 270 bottom
R1  0E  [RES0402_0-5]  86.36 130.95 90 top
R2  59E_1%  [RES0402_0-5]  11.7 127.78 180 top
R3  59E_1%  [RES0402_0-5]  13.7 127.78 180 top
R4  59E_1%  [RES0402_0-5]  21.61 127.78 180 top
R5  59E_1%  [RES0402_0-5]  23.6 127.78 180 top
R6  10K  [RES0402_0-5]  166.24 125.74 270 top
R7  10K  [RES0402_0-5]  169.16 125.87 0 top
R8  10K  [RES0402_0-5]  9.14 125.29 90 top
R9  10K  [RES0402_0-5]  19.05 125.29 90 top
R10  10E_1%  [RES0402_0-5]  88.9 122.57 270 top
R11  10E_1%  [RES0402_0-5]  86.11 122.44 270 top
R12  0E  [RES0402_0-5]  131.7 122.19 90 top
R13  0E  [RES0402_0-5]  129.29 121.93 90 top
R14  0E  [RES0402_0-5]  125.6 120.79 180 top
R15  220E  [RES0402_0-5]  122.43 120.54 0 top
R16  10K  [RES0402_0-5]  48.68 120.27 0 top
R17  10K  [RES0402_0-5]  112.85 120.22 270 top
R18  10K  [RES0402_0-5]  114.12 120.22 270 top
R19  2.2K  [RES0402_0-5]  73.22 120.16 0 top
R20  0E  [RES0402_0-5]  158.24 120.03 0 top
R21  10K  [RES0402_0-5]  61.2 119.87 90 top
R22  0.01E_0.5%  [RES1206-4TERM_0-75]  87.46 119.83 180 top
R23  10K  [RES0402_0-5]  42.93 119.65 0 top
R24  10K  [RES0402_0-5]  127.13 119.14 0 top
R25  10K  [RES0402_0-5]  102.56 118.57 90 top
R26  10K  [RES0402_0-5]  112.85 117.93 90 top
R27  10K  [RES0402_0-5]  114.24 117.93 90 top
R28  0E  [RES0402_0-5]  150.62 116.6 270 top
R29  100K  [RES0402_0-5]  77.85 113.17 180 top
R30  0E  [RES0402_0-5#2]  33.43 111.38 270 top
R31  2.49K_1%  [RES0402_0-5]  34.67 109.62 90 top
R32  2.49K_1%  [RES0402_0-5]  35.94 109.62 270 top
R33  2.49K_1%  [RES0402_0-5]  37.21 109.62 270 top
R34  2.49K_1%  [RES0402_0-5]  38.35 109.62 90 top
R35  2.49K_1%  [RES0402_0-5]  41.02 108.98 270 top
R36  2.49K_1%  [RES0402_0-5]  42.29 108.98 90 top
R37  220E  [RES0402_0-5#2]  30.53 108.6 180 top
R38  240E_1%  [RES0402_0-5]  96.52 107.33 90 top
R39  5.76K_1%  [RES0402_0-5]  43.64 106.95 90 top
R40  10K  [RES0402_0-5]  54.74 106.95 0 top
R41  2.49K_1%  [RES0402_0-5]  41.91 106.93 270 top
R42  2.2K  [RES0402_0-5#2]  37.59 106.88 90 top
R43  0E  [RES0402_0-5]  126.11 106.44 180 top
R44  10.1K_0.1%  [RES0603_0-75]  154.53 106.97 0 bottom
R45  10K  [RES0402_0-5]  54.74 105.68 180 top
R46  39.2E_1%  [RES0402_0-5]  84.08 104.92 180 top
R47  10K_1%  [RES0402_0-5]  136.02 104.66 270 top
R48  0E  [RES0402_0-5]  137.41 104.66 90 top
R49  162K_1%  [RES0402_0-5]  156.77 106.85 270 bottom
R50  100E  [RES0402_0-5]  64.9 104.15 180 top
R51  2.49K_1%  [RES0402_0-5]  47.62 104.08 180 top
R52  2.49K_1%  [RES0402_0-5]  44.83 103.96 0 top
R53  49.9E_1%  [RES0402_0-5]  54.74 103.52 180 top
R54  2.49K_1%  [RES0402_0-5]  47.62 102.94 0 top
R55  1K_1%  [RES0402_0-5]  64.9 102.88 0 top
R56  2.49K_1%  [RES0402_0-5]  44.87 102.85 180 top
R57  0E  [RES0402_0-5]  154.43 102.38 90 top
R58  100K  [RES0402_0-5]  155.7 102.38 270 top
R59  49.9E_1%  [RES0402_0-5]  59.18 100.85 270 top
R60  49.9E_1%  [RES0402_0-5]  60.45 100.85 270 top
R61  49.9E_1%  [RES0402_0-5]  61.72 100.85 270 top
R62  1K_1%  [RES0402_0-5]  96.45 100.54 270 top
R63  1K_1%  [RES0402_0-5]  97.72 100.54 90 top
R64  10K  [RES1206_0-75]  164.28 95.25 180 top
R65  49.9E_1%  [RES0402_0-5]  62.99 99.96 270 top
R66  2.2K  [RES0402_0-5]  83.95 98.86 90 top
R67  2.2K  [RES0402_0-5]  85.22 98.86 270 top
R68  10K  [RES0402_0-5]  73.45 98.82 180 top
R69  10K  [RES0402_0-5]  96.52 98.82 0 top
R70  11K_1%  [RES0402_0-5#2]  34.04 98.48 180 top
R71  39.2E_1%  [RES0402_0-5]  96.65 97.61 0 top
R72  10K  [RES0402_0-5]  73.45 97.55 180 top
R73  10E_1%  [RES0402_0-5]  125.73 97.42 270 top
R74  10E_1%  [RES0402_0-5]  129.29 97.42 270 top
R75  0E  [RES1210_0-75]  114.68 96.79 90 top
R76  220E  [RES0402_0-5#2]  30.23 96.28 90 top
R77  39.2E_1%  [RES0402_0-5]  96.65 96.39 0 top
R78  0E  [RES1210_0-75]  119.38 95.9 180 top
R79  2.2K  [RES0402_0-5#2]  38.48 95.77 270 top
R80  1K_1%  [RES0402_0-5]  174.37 95.77 180 top
R81  10K  [RES0402_0-5]  37.34 95.65 90 top
R82  2.05K_1%  [RES0402_0-5]  144.02 95.14 180 top
R83  39.2E_1%  [RES0402_0-5]  84.89 95.52 270 top
R84  39.2E_1%  [RES0402_0-5]  86.16 95.52 270 top
R85  39.2E_1%  [RES0402_0-5]  87.43 95.52 270 top
R86  39.2E_1%  [RES0402_0-5]  88.7 95.52 270 top
R87  39.2E_1%  [RES0402_0-5]  89.97 95.52 270 top
R88  39.2E_1%  [RES0402_0-5]  91.24 95.52 270 top
R89  39.2E_1%  [RES0402_0-5]  92.51 95.52 270 top
R90  39.2E_1%  [RES0402_0-5]  93.78 95.52 270 top
R91  39.2E_1%  [RES0402_0-5]  95.05 95.52 270 top
R92  0.002E_1%  [RES2512-4TERM_0-75]  127.51 91.96 270 top
R93  10K  [RES0402_0-5]  74.4 90.95 180 top
R94  2.49K_1%  [RES0402_0-5]  35.43 90 270 top
R95  2.49K_1%  [RES0402_0-5]  38.48 90 270 top
R96  2.49K_1%  [RES0402_0-5]  36.45 89.93 90 top
R97  2.49K_1%  [RES0402_0-5]  37.47 89.93 90 top
R98  10K  [RES0402_0-5]  74.4 89.68 180 top
R99  0E  [RES0402_0-5#2]  10.27 89.67 0 top
R100  2.49K_1%  [RES0402_0-5]  43.43 88.41 90 top
R101  2.49K_1%  [RES0402_0-5]  44.7 88.41 270 top
R102  10K  [RES0402_0-5]  31.62 87.9 0 top
R103  2.2K  [RES0402_0-5]  40.04 87.59 90 top
R104  10K  [RES0402_0-5#2]  38.71 87.53 270 top
R105  2.2K  [RES0402_0-5#2]  37.47 87.52 90 top
R106  0E  [RES1210_0-75]  121.03 86.25 180 top
R107  2.49K_1%  [RES0402_0-5]  46.23 84.59 0 top
R108  2.49K_1%  [RES0402_0-5]  46.23 83.45 0 top
R109  0E  [RES0402_0-5#2]  173.41 79.37 180 top
R110  11K_1%  [RES0402_0-5#2]  33.91 79.12 0 top
R111  0.015E_1%  [RES1206_1]  175.73 78.86 90 top
R112  49.9E_1%  [RES0402_0-5]  173.35 78.25 180 top
R113  0E  [RES0402_0-5#2]  147.07 76.09 0 top
R114  2.49K_1%  [RES0402_0-5]  41.27 76.68 90 top
R115  2.49K_1%  [RES0402_0-5]  42.55 76.68 270 top
R116  0.006E_1%  [RES1206_0-75]  141.35 76.47 270 top
R117  100K  [RES0402_0-5]  136.04 76.1 270 top
R118  24.9K_1%  [RES0402_0-5]  137.31 76.1 270 top
R119  49.9E_1%  [RES0402_0-5]  147.12 74.97 0 top
R120  10K  [RES0402_0-5]  46.51 87.72 270 top
R121  10K  [RES0402_0-5]  54.58 87.21 270 top
R122  0E  [RES0402_0-5]  138.05 73.55 180 top
R123  100K  [RES0402_0-5]  133.63 73.44 270 top
R124  10K  [RES0402_0-5]  120.14 69.86 270 top
R125  10K  [RES0402_0-5]  121.41 69.86 270 top
R126  2.49K_1%  [RES0402_0-5]  44.58 64.67 180 top
R127  0E  [RES0402_0-5]  133.1 64.28 270 top
R128  2.49K_1%  [RES0402_0-5]  44.58 63.52 180 top
R129  10.2E_1%  [RES0402_0-5#2]  168.3 63.46 270 top
R130  10.2E_1%  [RES0402_0-5#2]  157 63.02 0 top
R131  10K_1%  [RES0402_0-5#2]  150.84 62.96 90 top
R132  10K  [RES0402_0-5]  121.16 62.5 270 top
R133  10K  [RES0402_0-5]  122.43 62.5 90 top
R134  100K  [RES0402_0-5#2]  168.3 61.69 270 top
R135  2.49K_1%  [RES0402_0-5]  44.33 61.61 0 top
R136  0E  [RES0402_0-5]  10.71 59.52 90 top
R137  0E  [RES0402_0-5]  98.7 60.83 0 top
R138  0E  [RES0402_0-5]  99.19 60.34 90 top
R139  0E  [RES0402_0-5]  101.87 60.28 90 top
R140  0E  [RES0402_0-5]  102.36 60.77 180 top
R141  3.92K_1%  [RES0402_0-5]  167.54 59.65 270 top
R142  2.2K  [RES0402_0-5]  154.6 57.09 180 top
R143  10K  [RES0402_0-5]  139.45 57.04 0 top
R144  47.5K_1%  [RES0402_0-5]  131.44 56.91 270 top
R145  21K_1%  [RES0402_0-5]  132.97 56.02 270 top
R147  22E_1%  [RES0402_0-5]  86.87 52.85 90 top
R148  10K  [RES0402_0-5]  88.65 52.08 180 top
R150  4.7K  [RES0402_0-5]  66.17 49.54 0 top
R151  10K  [RES0402_0-5]  31.19 55.64 0 top
R152  22E_1%  [RES0402_0-5]  98.48 49.23 90 top
R153  10K  [RES0402_0-5]  21.67 55.77 0 top
R154  1K_1%  [RES0402_0-5]  96.7 50.14 90 top
R155  10K  [RES0402_0-5]  96.7 49.16 90 top
R156  10K  [RES0402_0-5]  103.5 47.26 180 top
R157  10E_1%  [RES0402_0-5]  93.85 45.86 0 top
R158  0E  [RES0402_0-5]  103.5 45.86 0 top
R159  49.9K_1%  [RES0402_0-5]  113.41 45.44 270 top
R160  49.9K_1%  [RES0402_0-5]  114.55 45.44 270 top
R161  49.9K_1%  [RES0402_0-5]  115.69 45.44 270 top
R162  49.9K_1%  [RES0402_0-5]  116.84 45.44 270 top
R163  49.9K_1%  [RES0402_0-5]  117.98 45.44 270 top
R164  49.9K_1%  [RES0402_0-5]  119.12 45.44 270 top
R165  49.9K_1%  [RES0402_0-5]  120.26 45.44 270 top
R166  49.9K_1%  [RES0402_0-5]  121.41 45.44 270 top
R167  100K  [RES0402_0-5]  91.9 45.37 270 top
R168  10K  [RES0402_0-5]  93.85 44.59 180 top
R169  10K  [RES0402_0-5]  103.5 44.46 180 top
R170  1M  [RES0603_0-75]  2.03 61.89 270 top
R171  0E  [RES0402_0-5]  142.49 43.65 270 top
R172  10K  [RES0402_0-5]  103.5 43.07 180 top
R173  10K  [RES0402_0-5]  103.5 41.67 180 top
R175  12K_1%  [RES0402_0-5]  135 41.16 90 top
R176  10K  [RES0402_0-5]  93.85 40.78 0 top
R177  0E  [RES0402_0-5]  74.42 38.11 90 top
R178  10K  [RES0402_0-5]  96.54 38.11 90 top
R179  10K  [RES0402_0-5]  97.81 38.11 90 top
R180  10K  [RES0402_0-5]  99.08 38.11 90 top
R181  10K  [RES0402_0-5]  100.35 38.11 90 top
R182  0E  [RES1206_0-75]  171.7 35.19 90 top
R183  10K  [RES0402_0-5]  109.98 33.03 90 top
R184  10K  [RES0402_0-5]  111.25 33.03 90 top
R185  10K  [RES0402_0-5]  67.81 32.55 0 top
R186  10K  [RES0402_0-5]  134.11 30.24 180 top
R187  10K  [RES0402_0-5]  71.33 29.97 90 top
R188  10K  [RES0402_0-5]  76.91 29.97 90 top
R189  100E  [RES0402_0-5]  73.16 29.48 0 top
R190  100E  [RES0402_0-5]  78.75 29.48 0 top
R191  10K  [RES0402_0-5]  132.21 28.97 180 top
R192  2.2K  [RES0402_0-5]  134.11 28.97 180 top
R193  10K  [RES0402_0-5]  117.86 28.72 180 top
R194  33E_1%  [RES0402_0-5]  71.72 22.23 90 top
R195  33E_1%  [RES0402_0-5]  77.31 22.23 90 top
R196  10K  [RES0402_0-5]  115.95 22.11 0 top
R197  220E  [RES0402_0-5]  99.97 19.53 270 top
R198  10K  [RES0402_0-5]  163.11 19.06 0 top
R199  10K  [RES0402_0-5]  163.11 17.79 0 top
R200  51E  [RES0402_0-5]  164.25 16.52 0 top
R201  220E  [RES0402_0-5]  53.98 16.04 90 top
R202  4.7K  [RES0402_0-5]  149.52 11.57 90 top
R203  4.7K  [RES0402_0-5]  150.79 11.57 90 top
R204  51K  [RES0402_0-5]  163.45 10.81 180 top
R205  4.87K_1%  [RES0402]  155.11 10.3 270 top
R206  1K_1%  [RES0402_0-5]  156.51 10.3 90 top
R207  1K_1%  [RES0402_0-5]  157.78 10.3 90 top
R208  1K_1%  [RES0402_0-5]  159.05 10.3 90 top
R209  1K_1%  [RES0402_0-5]  160.32 10.3 90 top
R210  220E  [RES0402_0-5]  97.31 9.84 90 top
R211  220E  [RES0402_0-5]  158.5 126 0 bottom
R212  220E  [RES0402_0-5]  31.5 124.98 180 bottom
R213  21K_1%  [RES0402_0-5]  98.31 119.55 270 bottom
R214  10.1K_0.1%  [RES0603_0-75]  98.37 122.06 180 bottom
R215  10E_1%  [RES0402_0-5]  152.04 121.17 270 bottom
R216  10E_1%  [RES0402_0-5]  149.29 121.17 270 bottom
R217  0E  [RES0402_0-5]  29.84 120.92 0 bottom
R218  10K  [RES0402_0-5]  57.55 120.17 180 bottom
R219  100K  [RES0402_0-5]  93.85 121.14 180 bottom
R220  0E  [RES0402_0-5]  24.51 120.14 90 bottom
R221  0E  [RES0402_0-5]  20.7 120.14 90 bottom
R222  0E  [RES0402_0-5]  14.6 120.14 90 bottom
R223  0E  [RES0402_0-5]  10.8 120.14 90 bottom
R224  10K  [RES0402_0-5]  112.85 119.19 90 bottom
